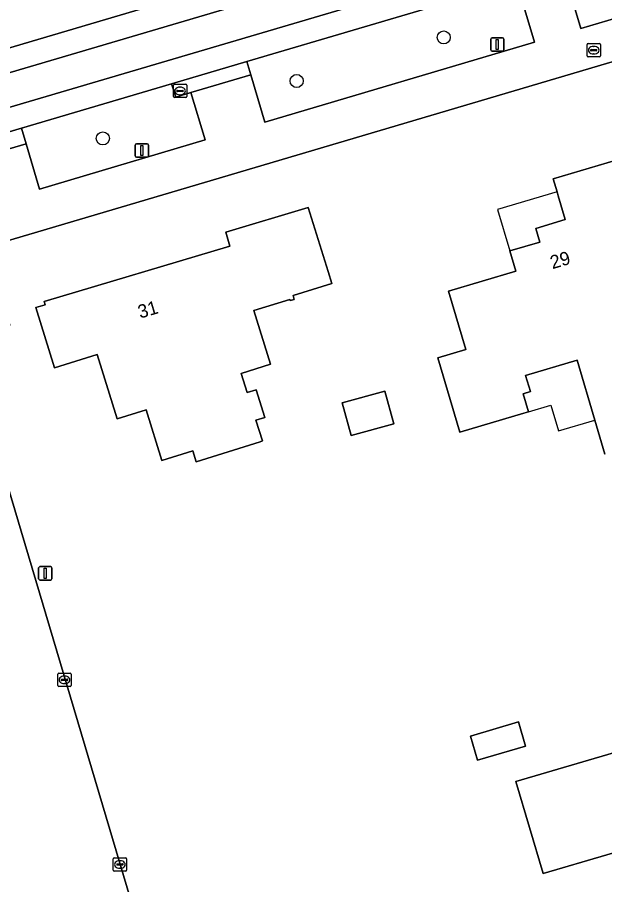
# Model space of a CAD drawing. Extents: x 162417 to 163722, y 384268 to 385417.
# Drawn here: x 163164.4 to 163208.3, y 384591.1 to 384656 of the extents above; entities that cross this region are included whole.
import ezdxf

# ---------------------------------------------------------------- set-up
doc = ezdxf.new("R2010")
doc.units = 0
for name, color, linetype in [('IMGEO_Boom', 7, 'Continuous'), ('IMGEO_Brandkraan', 7, 'Continuous'), ('IMGEO_Erf', 7, 'Continuous'), ('IMGEO_Groenvoorziening', 7, 'Continuous'), ('IMGEO_Kolk', 7, 'Continuous'), ('IMGEO_Lichtmast', 7, 'Continuous'), ('IMGEO_Loofbos', 7, 'Continuous'), ('IMGEO_Pand', 7, 'Continuous'), ('IMGEO_Pand_nummerreeks', 7, 'Continuous'), ('IMGEO_Pand_overbouw', 7, 'Continuous'), ('IMGEO_Rijbaan_lokaal_gesloten', 7, 'Continuous'), ('IMGEO_Rijbaan_lokaal_open', 7, 'Continuous'), ('IMGEO_Voetpad_open', 7, 'Continuous')]:
    doc.layers.add(name, color=color, linetype=linetype)

msp = doc.modelspace()

# ---------------------------------------------------------------- linework, layer by layer
at = {"layer": 'IMGEO_Boom'}
for centre in [(163196.31, 384654.463), (163185.315, 384651.206), (163170.825, 384646.915)]:
    msp.add_circle(centre, 0.489, dxfattribs=at)
at = {"layer": 'IMGEO_Brandkraan'}
for p, q in [((163207.025, 384653.083), (163207.025, 384653.935)), ((163207.1, 384654.009), (163207.952, 384654.009)), ((163207.513, 384653.789), (163207.538, 384653.789)), ((163208.026, 384653.935), (163208.026, 384653.083)), ((163207.284, 384653.503), (163207.284, 384653.515)), ((163207.722, 384653.466), (163207.324, 384653.466)), ((163207.327, 384653.552), (163207.725, 384653.552)), ((163207.536, 384653.229), (163207.511, 384653.229)), ((163207.768, 384653.515), (163207.768, 384653.503)), ((163207.952, 384653.009), (163207.1, 384653.009))]:
    msp.add_line(p, q, dxfattribs=at)
for points in [[(163207.025, 384653.083), (163207.025, 384653.935)], [(163207.1, 384654.009), (163207.952, 384654.009)], [(163208.026, 384653.935), (163208.026, 384653.083)], [(163207.952, 384653.009), (163207.1, 384653.009)]]:
    msp.add_lwpolyline(points, dxfattribs=at)
for centre, radius, start, end in [((163207.102, 384653.933), 0.0765, 91.55205, 178.44795), ((163207.102, 384653.933), 0.0765, 91.55205, 178.44795), ((163207.95, 384653.933), 0.0765, 1.55205, 88.44795), ((163207.95, 384653.933), 0.0765, 1.55205, 88.44795), ((163207.102, 384653.085), 0.0765, 181.55205, 268.44795), ((163207.102, 384653.085), 0.0765, 181.55205, 268.44795), ((163207.324, 384653.512), 0.0403, 85.87752, 175.75265), ((163207.321, 384653.502), 0.0366, 178.93798, 274.71019), ((163207.725, 384653.509), 0.043, 264.86636, 352.45326), ((163207.729, 384653.514), 0.0386, 1.73085, 96.63898), ((163207.95, 384653.085), 0.0765, 271.55205, 358.44795), ((163207.95, 384653.085), 0.0765, 271.55205, 358.44795)]:
    msp.add_arc(centre, radius, start, end, dxfattribs=at)
for centre, major_axis, ratio, start_param, end_param in [((163207.512, 384653.509), (-0.387, 0.002), 0.722429, 4.712389, 7.853982), ((163207.537, 384653.509), (-0.39, 0.002), 0.717154, 1.570796, 4.712389)]:
    msp.add_ellipse(centre, major_axis=major_axis, ratio=ratio, start_param=start_param, end_param=end_param, dxfattribs=at)
at = {"layer": 'IMGEO_Erf'}
for points in [[(163310.764, 384635.802), (163312.926, 384636.415), (163300.634, 384677.935), (163300.352, 384678.47), (163299.946, 384679.602), (163217.164, 384655.09), (163211.589, 384653.439), (163162.154, 384638.801), (163163.733, 384633.465), (163163.883, 384632.961), (163162.442, 384632.589), (163160.726, 384632.111), (163162.281, 384626.769), (163162.11, 384626.271), (163182.33, 384558.292), (163182.739, 384554.615), (163182.929, 384552.906)], [(163208.362, 384623.325), (163207.611, 384625.856), (163206.28, 384630.343), (163202.437, 384629.204), (163202.796, 384627.996), (163202.24, 384627.832), (163202.644, 384626.471), (163202.306, 384626.371), (163197.512, 384624.949), (163195.864, 384630.505), (163197.973, 384631.131), (163196.678, 384635.497), (163201.705, 384636.988), (163201.256, 384638.504), (163203.505, 384639.171), (163203.203, 384640.19), (163205.4, 384640.842), (163204.873, 384642.619), (163204.787, 384642.91), (163204.498, 384643.882), (163211.224, 384645.877)], [(163213.26, 384594.777), (163203.741, 384591.97), (163201.714, 384598.845), (163219.021, 384603.947)]]:
    msp.add_lwpolyline(points, dxfattribs=at)
for points in [[(163182.755, 384624.302), (163182.577, 384624.246), (163177.804, 384622.754), (163177.55, 384623.57), (163175.248, 384622.85), (163174.063, 384626.641), (163171.894, 384625.963), (163170.393, 384630.761), (163167.218, 384629.767), (163165.827, 384634.268), (163166.507, 384634.468), (163166.428, 384634.729), (163180.314, 384638.85), (163180.012, 384639.903), (163186.178, 384641.742), (163187.673, 384636.971), (163187.951, 384636.082), (163185.044, 384635.173), (163185.134, 384634.885), (163184.828, 384634.79), (163184.799, 384634.886), (163182.103, 384634.043), (163183.356, 384630.041), (163181.169, 384629.357), (163181.619, 384627.919), (163182.291, 384628.13), (163182.938, 384626.067), (163182.267, 384625.857)], [(163188.722, 384627.162), (163191.903, 384628.031), (163192.575, 384625.574), (163189.394, 384624.706)], [(163198.305, 384602.242), (163201.905, 384603.304), (163202.435, 384601.506), (163198.835, 384600.445)]]:
    msp.add_lwpolyline(points, close=True, dxfattribs=at)
at = {"layer": 'IMGEO_Groenvoorziening'}
for points in [[(163211.624, 384660.318), (163210.473, 384659.995), (163210.145, 384661.119), (163205.26, 384659.627), (163205.547, 384658.562), (163206.554, 384655.12), (163212.618, 384656.917)], [(163203.103, 384654.103), (163202.076, 384657.539), (163199.499, 384656.754), (163199.174, 384657.875), (163181.582, 384652.661), (163181.899, 384651.654), (163182.949, 384648.117)], [(163177.409, 384650.334), (163176.284, 384650.001), (163175.968, 384650.99), (163164.74, 384647.675), (163165.087, 384646.505), (163166.091, 384643.113), (163178.485, 384646.809)]]:
    msp.add_lwpolyline(points, close=True, dxfattribs=at)
at = {"layer": 'IMGEO_Kolk'}
for p, q in [((163176.098, 384650.036), (163176.098, 384650.888)), ((163176.173, 384650.962), (163177.025, 384650.962)), ((163176.357, 384650.456), (163176.357, 384650.468)), ((163176.795, 384650.419), (163176.397, 384650.419)), ((163176.4, 384650.505), (163176.798, 384650.505)), ((163176.586, 384650.742), (163176.611, 384650.742)), ((163176.841, 384650.468), (163176.841, 384650.456)), ((163177.099, 384650.888), (163177.099, 384650.036)), ((163177.025, 384649.962), (163176.173, 384649.962)), ((163176.609, 384650.182), (163176.584, 384650.182)), ((163167.457, 384606.023), (163167.457, 384606.875)), ((163167.532, 384606.949), (163168.384, 384606.949)), ((163167.716, 384606.443), (163167.716, 384606.455)), ((163168.154, 384606.406), (163167.756, 384606.406)), ((163167.759, 384606.492), (163168.157, 384606.492)), ((163167.945, 384606.729), (163167.97, 384606.729)), ((163168.2, 384606.455), (163168.2, 384606.443)), ((163168.458, 384606.875), (163168.458, 384606.023)), ((163168.384, 384605.949), (163167.532, 384605.949)), ((163167.968, 384606.169), (163167.943, 384606.169)), ((163171.604, 384592.224), (163171.604, 384593.076)), ((163171.679, 384593.15), (163172.531, 384593.15)), ((163172.092, 384592.93), (163172.117, 384592.93)), ((163172.605, 384593.076), (163172.605, 384592.224)), ((163172.531, 384592.15), (163171.679, 384592.15)), ((163171.863, 384592.644), (163171.863, 384592.656)), ((163172.301, 384592.607), (163171.903, 384592.607)), ((163171.906, 384592.693), (163172.304, 384592.693)), ((163172.115, 384592.37), (163172.09, 384592.37)), ((163172.347, 384592.656), (163172.347, 384592.644))]:
    msp.add_line(p, q, dxfattribs=at)
for points in [[(163176.098, 384650.036), (163176.098, 384650.888)], [(163176.173, 384650.962), (163177.025, 384650.962)], [(163177.099, 384650.888), (163177.099, 384650.036)], [(163177.025, 384649.962), (163176.173, 384649.962)], [(163167.457, 384606.023), (163167.457, 384606.875)], [(163167.532, 384606.949), (163168.384, 384606.949)], [(163168.458, 384606.875), (163168.458, 384606.023)], [(163168.384, 384605.949), (163167.532, 384605.949)], [(163171.604, 384592.224), (163171.604, 384593.076)], [(163171.679, 384593.15), (163172.531, 384593.15)], [(163172.605, 384593.076), (163172.605, 384592.224)], [(163172.531, 384592.15), (163171.679, 384592.15)]]:
    msp.add_lwpolyline(points, dxfattribs=at)
for centre, radius, start, end in [((163176.175, 384650.886), 0.0765, 91.55205, 178.44795), ((163176.175, 384650.886), 0.0765, 91.55205, 178.44795), ((163176.397, 384650.465), 0.0403, 85.87752, 175.75265), ((163176.394, 384650.455), 0.0366, 178.93798, 274.71019), ((163176.798, 384650.462), 0.043, 264.86636, 352.45326), ((163176.802, 384650.467), 0.0386, 1.73085, 96.63898), ((163177.023, 384650.886), 0.0765, 1.55205, 88.44795), ((163177.023, 384650.886), 0.0765, 1.55205, 88.44795), ((163176.175, 384650.038), 0.0765, 181.55205, 268.44795), ((163176.175, 384650.038), 0.0765, 181.55205, 268.44795), ((163177.023, 384650.038), 0.0765, 271.55205, 358.44795), ((163177.023, 384650.038), 0.0765, 271.55205, 358.44795), ((163167.534, 384606.873), 0.0765, 91.55205, 178.44795), ((163167.534, 384606.873), 0.0765, 91.55205, 178.44795), ((163167.756, 384606.452), 0.0403, 85.87752, 175.75265), ((163167.753, 384606.442), 0.0366, 178.93798, 274.71019), ((163168.157, 384606.449), 0.043, 264.86636, 352.45326), ((163168.161, 384606.454), 0.0386, 1.73085, 96.63898), ((163168.382, 384606.873), 0.0765, 1.55205, 88.44795), ((163168.382, 384606.873), 0.0765, 1.55205, 88.44795), ((163167.534, 384606.025), 0.0765, 181.55205, 268.44795), ((163167.534, 384606.025), 0.0765, 181.55205, 268.44795), ((163168.382, 384606.025), 0.0765, 271.55205, 358.44795), ((163168.382, 384606.025), 0.0765, 271.55205, 358.44795), ((163171.681, 384593.074), 0.0765, 91.55205, 178.44795), ((163171.681, 384593.074), 0.0765, 91.55205, 178.44795), ((163172.529, 384593.074), 0.0765, 1.55205, 88.44795), ((163172.529, 384593.074), 0.0765, 1.55205, 88.44795), ((163171.681, 384592.226), 0.0765, 181.55205, 268.44795), ((163171.681, 384592.226), 0.0765, 181.55205, 268.44795), ((163171.903, 384592.653), 0.0403, 85.87752, 175.75265), ((163171.9, 384592.643), 0.0366, 178.93798, 274.71019), ((163172.304, 384592.65), 0.043, 264.86636, 352.45326), ((163172.308, 384592.655), 0.0386, 1.73085, 96.63898), ((163172.529, 384592.226), 0.0765, 271.55205, 358.44795), ((163172.529, 384592.226), 0.0765, 271.55205, 358.44795)]:
    msp.add_arc(centre, radius, start, end, dxfattribs=at)
for centre, major_axis, ratio, start_param, end_param in [((163176.585, 384650.462), (-0.387, 0.002), 0.722429, 4.712389, 7.853982), ((163176.61, 384650.462), (-0.39, 0.002), 0.717154, 1.570796, 4.712389), ((163167.944, 384606.449), (-0.387, 0.002), 0.722429, 4.712389, 7.853982), ((163167.969, 384606.449), (-0.39, 0.002), 0.717154, 1.570796, 4.712389), ((163172.091, 384592.65), (-0.387, 0.002), 0.722429, 4.712389, 7.853982), ((163172.116, 384592.65), (-0.39, 0.002), 0.717154, 1.570796, 4.712389)]:
    msp.add_ellipse(centre, major_axis=major_axis, ratio=ratio, start_param=start_param, end_param=end_param, dxfattribs=at)
at = {"layer": 'IMGEO_Lichtmast'}
for p, q in [((163199.824, 384653.532), (163199.824, 384654.332)), ((163199.824, 384654.332), (163199.824, 384653.532)), ((163199.924, 384654.432), (163200.714, 384654.432)), ((163200.714, 384654.432), (163199.924, 384654.432)), ((163200.814, 384654.332), (163200.814, 384653.532)), ((163200.814, 384653.532), (163200.814, 384654.332)), ((163200.714, 384653.432), (163199.924, 384653.432)), ((163199.924, 384653.432), (163200.714, 384653.432)), ((163173.242, 384645.614), (163173.242, 384646.414)), ((163173.242, 384646.414), (163173.242, 384645.614)), ((163173.342, 384646.514), (163174.132, 384646.514)), ((163174.132, 384646.514), (163173.342, 384646.514)), ((163174.232, 384646.414), (163174.232, 384645.614)), ((163174.232, 384645.614), (163174.232, 384646.414)), ((163174.132, 384645.514), (163173.342, 384645.514)), ((163173.342, 384645.514), (163174.132, 384645.514)), ((163166.023, 384614.013), (163166.023, 384614.813)), ((163166.023, 384614.813), (163166.023, 384614.013)), ((163166.123, 384614.913), (163166.913, 384614.913)), ((163166.913, 384614.913), (163166.123, 384614.913)), ((163167.013, 384614.813), (163167.013, 384614.013)), ((163167.013, 384614.013), (163167.013, 384614.813)), ((163166.913, 384613.913), (163166.123, 384613.913)), ((163166.123, 384613.913), (163166.913, 384613.913))]:
    msp.add_line(p, q, dxfattribs=at)
for points in [[(163200.244, 384654.307), (163200.394, 384654.307), (163200.394, 384653.557), (163200.244, 384653.557), (163200.244, 384654.307)], [(163173.662, 384646.389), (163173.812, 384646.389), (163173.812, 384645.639), (163173.662, 384645.639), (163173.662, 384646.389)], [(163166.443, 384614.788), (163166.593, 384614.788), (163166.593, 384614.038), (163166.443, 384614.038), (163166.443, 384614.788)]]:
    msp.add_lwpolyline(points, dxfattribs=at)
for centre, start, end in [((163199.924, 384654.332), 90, 180), ((163199.924, 384654.332), 90, 180), ((163200.714, 384654.332), 0, 90), ((163200.714, 384654.332), 360, 90), ((163199.924, 384653.532), 180, 270), ((163199.924, 384653.532), 180, 270), ((163200.714, 384653.532), 270, 0), ((163200.714, 384653.532), 270, 0), ((163173.342, 384646.414), 90, 180), ((163173.342, 384646.414), 90, 180), ((163174.132, 384646.414), 0, 90), ((163174.132, 384646.414), 360, 90), ((163173.342, 384645.614), 180, 270), ((163173.342, 384645.614), 180, 270), ((163174.132, 384645.614), 270, 0), ((163174.132, 384645.614), 270, 0), ((163166.123, 384614.813), 90, 180), ((163166.123, 384614.813), 90, 180), ((163166.913, 384614.813), 0, 90), ((163166.913, 384614.813), 360, 90), ((163166.123, 384614.013), 180, 270), ((163166.123, 384614.013), 180, 270), ((163166.913, 384614.013), 270, 0), ((163166.913, 384614.013), 270, 0)]:
    msp.add_arc(centre, 0.1, start, end, dxfattribs=at)
at = {"layer": 'IMGEO_Loofbos'}
msp.add_lwpolyline([(163117.805, 384640.109), (163119.063, 384640.452), (163198.09, 384663.826), (163199.163, 384664.143)], dxfattribs=at)
at = {"layer": 'IMGEO_Pand'}
for points in [[(163211.224, 384645.877), (163204.498, 384643.882), (163204.787, 384642.91), (163204.873, 384642.619), (163205.4, 384640.842), (163203.203, 384640.19), (163203.505, 384639.171), (163201.256, 384638.504), (163201.705, 384636.988), (163196.678, 384635.497), (163197.973, 384631.131), (163195.864, 384630.505), (163197.512, 384624.949), (163202.306, 384626.371), (163202.644, 384626.471), (163202.24, 384627.832), (163202.796, 384627.996), (163202.437, 384629.204), (163206.28, 384630.343), (163207.611, 384625.856), (163208.362, 384623.325)], [(163219.021, 384603.947), (163201.714, 384598.845), (163203.741, 384591.97), (163213.26, 384594.777)]]:
    msp.add_lwpolyline(points, dxfattribs=at)
for points in [[(163182.755, 384624.302), (163182.267, 384625.857), (163182.938, 384626.067), (163182.291, 384628.13), (163181.619, 384627.919), (163181.169, 384629.357), (163183.356, 384630.041), (163182.103, 384634.043), (163184.799, 384634.886), (163184.828, 384634.79), (163185.134, 384634.885), (163185.044, 384635.173), (163187.951, 384636.082), (163187.673, 384636.971), (163186.178, 384641.742), (163180.012, 384639.903), (163180.314, 384638.85), (163166.428, 384634.729), (163166.507, 384634.468), (163165.827, 384634.268), (163167.218, 384629.767), (163170.393, 384630.761), (163171.894, 384625.963), (163174.063, 384626.641), (163175.248, 384622.85), (163177.55, 384623.57), (163177.804, 384622.754), (163182.577, 384624.246)], [(163188.722, 384627.162), (163189.394, 384624.706), (163192.575, 384625.574), (163191.903, 384628.031)], [(163198.305, 384602.242), (163198.835, 384600.445), (163202.435, 384601.506), (163201.905, 384603.304)]]:
    msp.add_lwpolyline(points, close=True, dxfattribs=at)
at = {"layer": 'IMGEO_Pand_overbouw'}
for points in [[(163205.4, 384640.842), (163204.787, 384642.91), (163200.342, 384641.591), (163201.256, 384638.504), (163203.505, 384639.171), (163203.203, 384640.19)], [(163206.28, 384630.343), (163202.437, 384629.204), (163202.796, 384627.996), (163202.24, 384627.832), (163202.644, 384626.471), (163204.327, 384626.97), (163204.896, 384625.051), (163207.611, 384625.856)]]:
    msp.add_lwpolyline(points, close=True, dxfattribs=at)
at = {"layer": 'IMGEO_Rijbaan_lokaal_gesloten'}
for points in [[(163119.063, 384640.452), (163119.605, 384638.786), (163198.603, 384662.094), (163198.09, 384663.826)], [(163121.609, 384634.98), (163143.923, 384641.535), (163164.74, 384647.675), (163175.968, 384650.99), (163181.582, 384652.661), (163199.174, 384657.875), (163199.805, 384658.057), (163199.311, 384659.719), (163120.305, 384636.428), (163120.782, 384634.728)]]:
    msp.add_lwpolyline(points, close=True, dxfattribs=at)
msp.add_lwpolyline([(163182.739, 384554.615), (163182.33, 384558.292), (163162.11, 384626.271), (163160.428, 384632.021), (163157.808, 384631.227), (163158.677, 384628.287)], dxfattribs=at)
at = {"layer": 'IMGEO_Rijbaan_lokaal_open'}
msp.add_lwpolyline([(163199.311, 384659.719), (163198.603, 384662.094), (163119.605, 384638.786), (163120.305, 384636.428)], close=True, dxfattribs=at)
at = {"layer": 'IMGEO_Voetpad_open'}
for points in [[(163202.076, 384657.539), (163203.103, 384654.103), (163182.949, 384648.117), (163181.899, 384651.654), (163177.409, 384650.334), (163178.485, 384646.809), (163166.091, 384643.113), (163165.087, 384646.505), (163158.886, 384644.69), (163160.563, 384638.902), (163161.642, 384639.207), (163161.818, 384638.702), (163162.154, 384638.801), (163211.589, 384653.439), (163217.164, 384655.09), (163299.946, 384679.602)], [(163212.618, 384656.917), (163206.554, 384655.12), (163205.547, 384658.562)]]:
    msp.add_lwpolyline(points, dxfattribs=at)
for points in [[(163177.409, 384650.334), (163181.899, 384651.654), (163181.582, 384652.661), (163175.968, 384650.99), (163176.284, 384650.001)], [(163144.258, 384640.408), (163148.129, 384641.541), (163158.886, 384644.69), (163165.087, 384646.505), (163164.74, 384647.675), (163143.923, 384641.535)]]:
    msp.add_lwpolyline(points, close=True, dxfattribs=at)

# ---------------------------------------------------------------- texts
at = {"layer": 'IMGEO_Pand_nummerreeks'}
for s, rotation, p in [('29', 16.52983, (163204.443, 384637.137)), ('31', 16.52951, (163173.62, 384633.442))]:
    msp.add_text(s, height=1, rotation=rotation, dxfattribs=at).set_placement(p)

doc.saveas('drawing.dxf')
